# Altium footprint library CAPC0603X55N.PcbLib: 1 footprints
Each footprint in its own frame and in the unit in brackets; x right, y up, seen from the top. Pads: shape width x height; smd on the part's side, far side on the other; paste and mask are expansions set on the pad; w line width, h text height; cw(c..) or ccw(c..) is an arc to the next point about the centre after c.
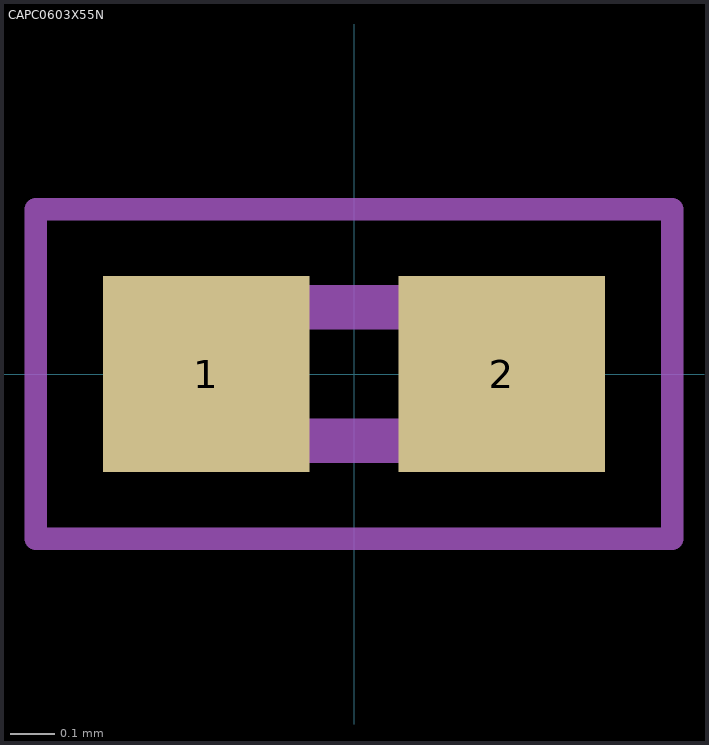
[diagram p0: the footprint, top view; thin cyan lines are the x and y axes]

## CAPC0603X55N [mm]
pads (2):
  rect 0.465x0.44 smd: 1(-0.332,0) 2(0.332,0)
Mechanical 15:
  lines w0.1: -0.3,-0.15 0.3,-0.15 0.3,0.15 -0.3,0.15 -0.3,-0.15
Mechanical 20:
  lines w0.05: -0.715,-0.37 0.715,-0.37 0.715,0.37 -0.715,0.37 -0.715,-0.37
